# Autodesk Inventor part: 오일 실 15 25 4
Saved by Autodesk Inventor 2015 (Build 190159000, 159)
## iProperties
Created: 2024-11
Part Number: 오일 실 15 25 4
Material: 일반
Document SubType Name: Modeling
Designer: 102-5
Density: 1 g/cm^3
Appearance: 기본값
Author: 102-5
Author: jhkim
Description: 오일 실 - 비스프링, 조립 GA
Creation Date: 2024-10-25
Sending System: Autodesk Inventor 2025
Preprocessor: ST-DEVELOPER v20
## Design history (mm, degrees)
node "오일 실 15 25 41"
body "Solid1"
node "기준1"
